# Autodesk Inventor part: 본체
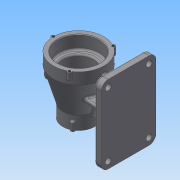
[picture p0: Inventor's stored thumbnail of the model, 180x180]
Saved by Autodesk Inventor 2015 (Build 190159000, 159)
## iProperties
Created: 2020-03
Part Number: 본체
Material: 일반
Document SubType Name: Modeling
Designer: user
Density: 1 g/cm^3
Appearance: 기본값
Author: user
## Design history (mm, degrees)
sketch "스케치1"
  geometry: L1 (0, 0)-(0, 100); L2 (0, 100)-(44, 100); L3 (0, 0)-(27.5, 0); L4 (27.5, 0)-(27.5, 23); L5 (44, 100)-(44, 80); L6 (44, 80)-(27.5, 23)
  constraints: 12 end point, 2 horizontal, 2 vertical, 1 perpendicular
  dimensions: "d0" = 100 distance of L1.start L1.end; "d1" = 44 distance of L1.end L2.end; "d3" = 27.5 distance of L1.start L3.end; "d4" = 23 distance of L3.end L4.end; "d5" = 20 distance of L2.end L5.end
revolve "회전1" sketch "스케치1" stored, may be unused: angle "d6" = 90 deg
hole "구멍1" diameter "d9" = 72; stored, may be unused: countersink angle "d13" = 90 deg, drill point angle "d15" = 0 deg; dims "d7" = 10, "d8" = 10, "d10" = 6, "d11" = 4, "d12" = 2, "d14" = 23
hole "구멍2" diameter "d18" = 52; stored, may be unused: countersink angle "d22" = 90 deg, drill point angle "d24" = 0 deg; dims "d16" = 10, "d17" = 10, "d19" = 6, "d20" = 4, "d21" = 2, "d23" = 47
hole "구멍3" diameter "d27" = 40; stored, may be unused: countersink angle "d31" = 90 deg, drill point angle "d33" = 0 deg; dims "d25" = 10, "d26" = 10, "d28" = 6, "d29" = 4, "d30" = 2, "d32" = 30
chamfer "모따기1" distance "d34" = 1; stored, may be unused: second distance "d35" = 2, angle "d36" = 45 deg
chamfer "모따기2" distance "d37" = 1; stored, may be unused: second distance "d38" = 2, angle "d39" = 45 deg
fillet "모깎기1" dims "d40" = 3
node "작업 평면1"
sketch "스케치2"
  geometry: L1 (-47.5, -16)-(-47.5, 119); L2 (47.5, -16)-(47.5, 119); L3 (-27.5, 23)-(27.5, 23) reference; L4 (-44, 80)-(44, 80) reference; L5 (-44, 80)-(-27.5, 23) reference; L6 (44, 80)-(27.5, 23) reference; L7 (-44, 80)-(44, 80) reference; L8 (-44, 100)-(44, 100) reference; L9 (-27.5, 0)-(27.5, 0) reference; L10 (-27.5, 0)-(27.5, 0) reference; L11 (-27.5, 23)-(27.5, 23) reference; L12 (-35.75, 51.5)-(-47.5, 51.5); L13 (47.5, 119)-(-47.5, 119); L14 (47.5, -16)-(-47.5, -16); 1 further point
  constraints: 10 end point, 3 parallel, 2 midpoint, 1 perpendicular
  dimensions: "d43" = 95 distance between parallel lines of L1 L2; "d44" = 67.5 distance between parallel lines of L12 L13; "d45" = 67.5 distance between parallel lines of L12 L14
extrude "돌출1" join sketch "스케치2" distance "d46" = 12; taper "d47" = 0 deg
fillet "모깎기2" dims "d48" = 12
fillet "모깎기3" dims "d49" = 3
sketch "스케치3"
  geometry: L1 (51.5, 4)-(51.5, -4); L2 (14.5, 4)-(14.5, -4); L3 (88.5, 4)-(88.5, -4); L4 (14.5, 0)-(88.5, 0); L5 (14.5, 4)-(88.5, 4); L6 (14.5, -4)-(88.5, -4); 1 further point
  constraints: 12 end point, 4 midpoint, 4 parallel
  dimensions: "d50" = 37 distance between parallel lines of L1 L2; "d51" = 37 distance between parallel lines of L1 L3; "d52" = 4 distance between parallel lines of L4 L5; "d53" = 4 distance between parallel lines of L4 L6
extrude "돌출2" join sketch "스케치3" stored distance "d54" = 12; taper "d55" = 0 deg
node "작업 평면2"
sketch "스케치4"
  geometry: L1 (0, 39.5)-(0, -31.5) reference; L2 (0, 8)-(31.182, 8) reference; L3 (0, 0)-(31.182, 0) reference; L4 (0, 29)-(50.148, 24.613); L5 (0, -21)-(50.148, -16.613); L6 (31.182, 8)-(47.792, 8) reference; L7 (47.792, 0)-(31.182, 0) reference; L8 (39.223, 8)-(0, 8); L9 (39.223, 0)-(0, 0); C1 r 36 at (75, 4) reference; A1 r 44 centre (75, 4) between (31.182, 0) and (31.182, 8) reference; A2 r 32.288 centre (75, 4) between (50.148, 24.613) and (50.148, -16.613); 3 further points
  constraints: 8 end point, 4 point on line, 2 point on circle, 1 centre point, 1 coincident, 1 collinear, 1 horizontal
  dimensions: "d58" = 95 deg angle of L1 L4
extrude "돌출4" join sketch "스케치4" stored distance "d63" = 8; taper "d64" = 0 deg
fillet "모깎기4" dims "d65" = 3
fillet "모깎기5" dims "d66" = 3
sketch "스케치5"
  geometry: C1 r 5 at (107, -35.5); C2 r 5 at (107, 35.5); C3 r 5 at (-4, 35.5); C4 r 5 at (-4, -35.5); A1 r 9 centre (107, -35.5) between (107, -44.5) and (116, -35.5) reference; A2 r 9 centre (107, 35.5) between (116, 35.5) and (107, 44.5) reference; A3 r 9 centre (-4, 35.5) between (-4, 44.5) and (-13, 35.5) reference; A4 r 9 centre (-4, -35.5) between (-13, -35.5) and (-4, -44.5) reference; 1 further point
  constraints: 4 centre point, 4 coincident
  dimensions: "d67" = 10 diameter of C1; "d68" = 10 diameter of C2; "d69" = 10 diameter of C3; "d70" = 10 diameter of C4
extrude "돌출5" cut sketch "스케치5" distance "d71" = 12; taper "d72" = 0 deg
node "작업 평면3"
sketch "스케치6"
  geometry: L1 (-116, 35.5)-(-116, -35.5) reference; L2 (4, 44.5)-(-107, 44.5) reference; L3 (13, -35.5)-(13, 35.5) reference; L4 (-107, -44.5)-(4, -44.5) reference; L5 (-91.5, -1)-(-91.5, 1) reference; L6 (-58.5, -7)-(-85.5, -7) reference; L7 (-58.5, -21.726)-(-58.5, -7) reference; L8 (-50.5, -27.749)-(-52.5, -27.749) reference; L9 (-44.5, -7)-(-44.5, -21.726) reference; L10 (-17.5, -7)-(-44.5, -7) reference; L11 (-11.5, 1)-(-11.5, -1) reference; L12 (-44.5, 7)-(-17.5, 7) reference; L13 (-44.5, 21.726)-(-44.5, 7) reference; L14 (-52.5, 27.749)-(-50.5, 27.749) reference; L15 (-58.5, 7)-(-58.5, 21.726) reference; L16 (-85.5, 7)-(-58.5, 7) reference; L17 (-91.5, 0)-(-11.5, 0); L18 (-51.5, 27.749)-(-51.5, -27.749); C1 r 5 at (4, 35.5) reference; C2 r 5 at (-107, -35.5) reference; C3 r 5 at (-107, 35.5) reference; C4 r 5 at (4, -35.5) reference; C5 r 15 at (-51.5, 0); A1 r 9 centre (-107, -35.5) between (-116, -35.5) and (-107, -44.5) reference; A2 r 9 centre (-107, 35.5) between (-107, 44.5) and (-116, 35.5) reference; A3 r 9 centre (4, 35.5) between (13, 35.5) and (4, 44.5) reference; A4 r 9 centre (4, -35.5) between (4, -44.5) and (13, -35.5) reference; A5 r 6 centre (-85.5, 1) between (-85.5, 7) and (-91.5, 1) reference; A6 r 6 centre (-85.5, -1) between (-91.5, -1) and (-85.5, -7) reference; A7 r 6 centre (-17.5, -1) between (-17.5, -7) and (-11.5, -1) reference; A8 r 6 centre (-17.5, 1) between (-11.5, 1) and (-17.5, 7) reference; 5 further points; 4 other entities
  constraints: 5 midpoint, 4 end point, 1 centre point, 4 other
  dimensions: "d74" = 30 diameter of C5
extrude "돌출6" join sketch "스케치6" stored distance "d75" = 12; taper "d76" = 0 deg
hole "구멍4" diameter "d79" = 20; stored, may be unused: countersink angle "d83" = 90 deg, drill point angle "d85" = 0 deg; dims "d77" = 10, "d78" = 10, "d80" = 6, "d81" = 4, "d82" = 2, "d84" = 30
chamfer "모따기3" distance "d86" = 1; stored, may be unused: second distance "d87" = 2, angle "d88" = 45 deg
sketch "스케치7"
  geometry: L1 (0, 0)-(-62.801, 0); C1 r 37 at (0, 0) reference; C2 r 3.5 at (-44, 0); C3 r 3.5 at (22, -38.105); C4 r 3.5 at (22, 38.105); 1 further point
  constraints: 3 centre point, 2 end point, 1 horizontal, 1 horizontal alignment, 1 point on line, 8 other
  dimensions: "d89" = 7 diameter of C2; "d92" = 360 deg dimension on point (0, 0) C2.centre (derived)
extrude "돌출7" join sketch "스케치7" distance "d94" = 15; taper "d95" = 0 deg
fillet "모깎기6" dims "d96" = 3
fillet "모깎기7" dims "d7" = 10, "d8" = 10, "d27" = 40, "d47" = 0, "d49" = 3, "d70" = 10, "d95" = 0, "d97" = 3
fillet "모깎기8" dims "d98" = 1
sketch "스케치8"
  geometry: C1 r 1.474 at (0, 0); A1 r 3.5 centre (0, 0) between (-0.608, 3.447) and (-0.608, -3.447) reference
  constraints: 1 centre point, 1 coincident
hole "구멍5" sketch "스케치8" at (0, 0) diameter "d99" = 4.134; stored, may be unused: countersink angle "d103" = 90 deg, drill point angle "d105" = 118 deg; dims "d100" = 10, "d101" = 4, "d102" = 2, "d104" = 11
sketch "스케치9"
  geometry: L1 (0, 0)-(37.161, 0); C1 r 21 at (0, 0) reference; C2 r 3.5 at (27.5, 0); 1 further point
  constraints: 2 end point, 1 centre point, 1 horizontal, 1 horizontal alignment, 1 point on line, 1 other
  dimensions: "d109" = 7 diameter of C2
extrude "돌출8" join sketch "스케치9" distance "d110" = 15; taper "d111" = 0 deg
fillet "모깎기9" dims "d115" = 3
fillet "모깎기10" dims "d116" = 1
sketch "스케치10"
  geometry: C1 r 1.816 at (0, 0); A1 r 3.5 centre (0, 0) between (0.506, -3.463) and (0.506, 3.463) reference
  constraints: 1 centre point, 1 coincident
hole "구멍6" sketch "스케치10" at (0, 0) diameter "d117" = 4.134; stored, may be unused: countersink angle "d121" = 90 deg, drill point angle "d123" = 118 deg; dims "d118" = 10, "d119" = 4, "d120" = 2, "d122" = 11
sketch "스케치11"
  geometry: L1 (52.5, 27.749)-(50.5, 27.749) reference; L2 (107, 47.5)-(-4, 47.5) reference; L3 (51.5, 27.749)-(51.5, 57.771); L4 (107, 37.5)-(-4, 37.5); 3 further points
  constraints: 4 end point, 2 midpoint, 1 coincident, 1 parallel, 1 vertical, 1 other
  dimensions: "d127" = 10 distance between parallel lines of L2 L4
feature "엠보싱1" sketch "스케치11" dims "d0" = 100, "d1" = 44, "d3" = 27.5, "d4" = 23, "d5" = 20, "d128" = 0.5, "d129" = 0
node "솔리드1"
pattern_circular "원형 패턴1" dims angle "d107" = 360 deg
pattern_circular "원형 패턴2" dims angle "d113" = 360 deg
pattern_circular "원형 패턴3" dims angle "d125" = 360 deg
node "투영된 루프1"
node "투영된 루프2"
node "투영된 루프3"
node "투영된 루프4"
other parameters: "d41" = 87, "d62" = 8, "d73" = -132
